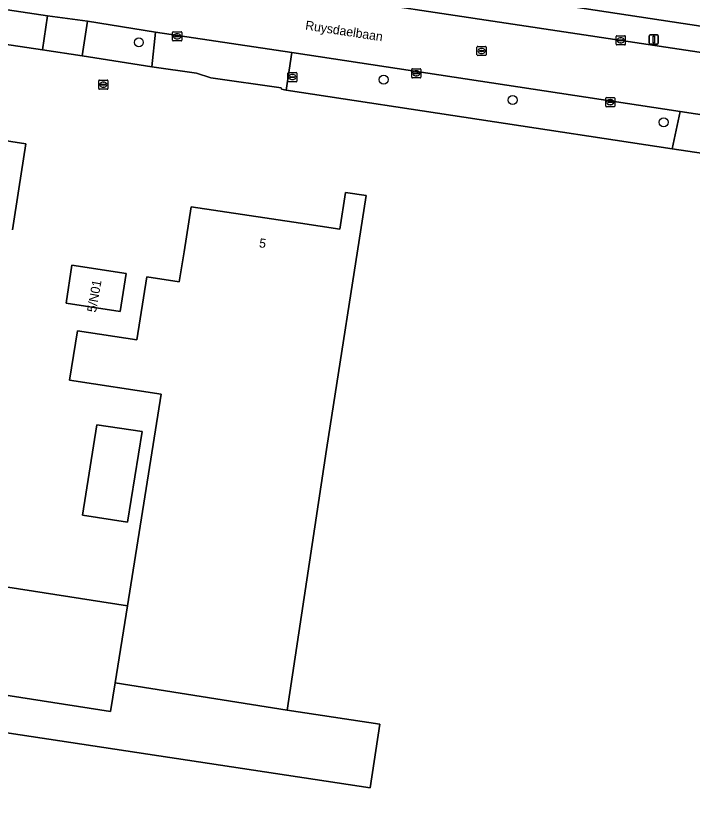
# Model space of a CAD drawing. Extents: x 163008 to 163854, y 382777 to 383982.
# Drawn here: x 163408.4 to 163482.5, y 382906.1 to 382991.6 of the extents above; entities that cross this region are included whole.
import ezdxf

# ---------------------------------------------------------------- set-up
doc = ezdxf.new("R2010")
doc.units = 0
for name, color, linetype in [('IMGEO_Berm_groen', 7, 'Continuous'), ('IMGEO_Boom', 7, 'Continuous'), ('IMGEO_Brandkraan', 7, 'Continuous'), ('IMGEO_Erf', 7, 'Continuous'), ('IMGEO_Fietspad_gesloten', 7, 'Continuous'), ('IMGEO_Kolk', 7, 'Continuous'), ('IMGEO_Lichtmast', 7, 'Continuous'), ('IMGEO_Muur', 7, 'Continuous'), ('IMGEO_Openbare_ruimte_label', 7, 'Continuous'), ('IMGEO_Pand', 7, 'Continuous'), ('IMGEO_Pand_nummerreeks', 7, 'Continuous'), ('IMGEO_Rijbaan_lokaal_gesloten', 7, 'Continuous'), ('IMGEO_Rioolput', 7, 'Continuous'), ('IMGEO_Voetpad_open', 7, 'Continuous')]:
    doc.layers.add(name, color=color, linetype=linetype)

msp = doc.modelspace()

# ---------------------------------------------------------------- linework, layer by layer
at = {"layer": 'IMGEO_Berm_groen'}
for points in [[(163489.468, 382989.524), (163415.977, 383000.7), (163414.901, 382999.838), (163414.341, 382999.01)], [(163415.02, 382997.894), (163488.831, 382986.752)]]:
    msp.add_lwpolyline(points, dxfattribs=at)
at = {"layer": 'IMGEO_Boom'}
for centre in [(163421.921, 382988.663), (163448.722, 382984.588), (163462.851, 382982.356), (163479.379, 382979.918)]:
    msp.add_circle(centre, 0.489, dxfattribs=at)
at = {"layer": 'IMGEO_Brandkraan'}
for p, q in [((163438.231, 382984.437), (163438.231, 382985.289)), ((163438.306, 382985.363), (163439.158, 382985.363)), ((163439.232, 382985.289), (163439.232, 382984.437)), ((163439.158, 382984.363), (163438.306, 382984.363)), ((163438.49, 382984.857), (163438.49, 382984.869)), ((163438.928, 382984.82), (163438.53, 382984.82)), ((163438.533, 382984.906), (163438.931, 382984.906)), ((163438.742, 382984.583), (163438.717, 382984.583)), ((163438.719, 382985.143), (163438.744, 382985.143)), ((163438.974, 382984.869), (163438.974, 382984.857))]:
    msp.add_line(p, q, dxfattribs=at)
for points in [[(163438.231, 382984.437), (163438.231, 382985.289)], [(163438.306, 382985.363), (163439.158, 382985.363)], [(163439.232, 382985.289), (163439.232, 382984.437)], [(163439.158, 382984.363), (163438.306, 382984.363)]]:
    msp.add_lwpolyline(points, dxfattribs=at)
for centre, radius, start, end in [((163438.308, 382985.287), 0.0765, 91.55205, 178.44795), ((163438.308, 382985.287), 0.0765, 91.55205, 178.44795), ((163439.156, 382985.287), 0.0765, 1.55205, 88.44795), ((163439.156, 382985.287), 0.0765, 1.55205, 88.44795), ((163438.308, 382984.439), 0.0765, 181.55205, 268.44795), ((163438.308, 382984.439), 0.0765, 181.55205, 268.44795), ((163438.53, 382984.866), 0.0403, 85.87752, 175.75265), ((163438.527, 382984.856), 0.0366, 178.93798, 274.71019), ((163438.931, 382984.863), 0.043, 264.86636, 352.45326), ((163438.935, 382984.868), 0.0386, 1.73085, 96.63898), ((163439.156, 382984.439), 0.0765, 271.55205, 358.44795), ((163439.156, 382984.439), 0.0765, 271.55205, 358.44795)]:
    msp.add_arc(centre, radius, start, end, dxfattribs=at)
for centre, major_axis, ratio, start_param, end_param in [((163438.718, 382984.863), (-0.387, 0.002), 0.722429, 4.712389, 7.853982), ((163438.743, 382984.863), (-0.39, 0.002), 0.717154, 1.570796, 4.712389)]:
    msp.add_ellipse(centre, major_axis=major_axis, ratio=ratio, start_param=start_param, end_param=end_param, dxfattribs=at)
at = {"layer": 'IMGEO_Erf'}
for points in [[(163528.59, 382970.003), (163520.158, 382971.27), (163505.535, 382973.466), (163495.471, 382975.027), (163495.486, 382974.762), (163480.305, 382977.026), (163438.054, 382983.442), (163437.535, 382983.552), (163437.517, 382983.673), (163429.788, 382984.796), (163428.242, 382985.302), (163423.358, 382986.004), (163415.703, 382987.189), (163411.357, 382987.861), (163338.968, 382998.653)], [(163388.438, 382980.834), (163409.558, 382977.575), (163408.795, 382972.634), (163408.102, 382968.143)], [(163402.396, 382929.842), (163420.669, 382927.024), (163424.375, 382950.167), (163414.343, 382951.716), (163415.208, 382957.117), (163421.702, 382956.115), (163422.808, 382963.027), (163426.346, 382962.481), (163426.869, 382965.744), (163427.66, 382970.681), (163439.625, 382968.876), (163443.926, 382968.227), (163444.531, 382972.24), (163446.825, 382971.895), (163442.466, 382944.136), (163438.164, 382915.609), (163448.299, 382914.081), (163447.247, 382907.102), (163404.085, 382913.618)]]:
    msp.add_lwpolyline(points, dxfattribs=at)
for points in [[(163413.947, 382960.143), (163414.588, 382964.296), (163420.534, 382963.378), (163419.893, 382959.225)], [(163420.687, 382936.178), (163415.745, 382936.94), (163417.329, 382946.834), (163422.271, 382946.072)]]:
    msp.add_lwpolyline(points, close=True, dxfattribs=at)
at = {"layer": 'IMGEO_Fietspad_gesloten'}
msp.add_lwpolyline([(163414.341, 382999.01), (163414.901, 382999.838), (163415.977, 383000.7), (163489.468, 382989.524), (163489.768, 382988.576), (163489.787, 382987.615)], dxfattribs=at)
at = {"layer": 'IMGEO_Kolk'}
for p, q in [((163425.617, 382988.898), (163425.617, 382989.75)), ((163425.692, 382989.824), (163426.544, 382989.824)), ((163426.105, 382989.604), (163426.13, 382989.604)), ((163426.618, 382989.75), (163426.618, 382988.898)), ((163426.544, 382988.824), (163425.692, 382988.824)), ((163425.876, 382989.318), (163425.876, 382989.33)), ((163426.314, 382989.281), (163425.916, 382989.281)), ((163425.919, 382989.367), (163426.317, 382989.367)), ((163426.128, 382989.044), (163426.103, 382989.044)), ((163426.36, 382989.33), (163426.36, 382989.318)), ((163474.179, 382988.458), (163474.179, 382989.31)), ((163474.254, 382989.384), (163475.106, 382989.384)), ((163474.438, 382988.878), (163474.438, 382988.89)), ((163474.876, 382988.841), (163474.478, 382988.841)), ((163474.481, 382988.927), (163474.879, 382988.927)), ((163474.667, 382989.164), (163474.692, 382989.164)), ((163474.922, 382988.89), (163474.922, 382988.878)), ((163475.18, 382989.31), (163475.18, 382988.458)), ((163475.106, 382988.384), (163474.254, 382988.384)), ((163474.69, 382988.604), (163474.665, 382988.604)), ((163451.794, 382984.852), (163451.794, 382985.704)), ((163451.869, 382985.778), (163452.721, 382985.778)), ((163452.053, 382985.272), (163452.053, 382985.284)), ((163452.491, 382985.235), (163452.093, 382985.235)), ((163452.096, 382985.321), (163452.494, 382985.321)), ((163452.282, 382985.558), (163452.307, 382985.558)), ((163452.537, 382985.284), (163452.537, 382985.272)), ((163452.795, 382985.704), (163452.795, 382984.852)), ((163452.721, 382984.778), (163451.869, 382984.778)), ((163452.305, 382984.998), (163452.28, 382984.998)), ((163473.032, 382981.697), (163473.032, 382982.549)), ((163473.107, 382982.623), (163473.959, 382982.623)), ((163473.291, 382982.117), (163473.291, 382982.129)), ((163473.729, 382982.08), (163473.331, 382982.08)), ((163473.334, 382982.166), (163473.732, 382982.166)), ((163473.543, 382981.843), (163473.518, 382981.843)), ((163473.52, 382982.403), (163473.545, 382982.403)), ((163473.775, 382982.129), (163473.775, 382982.117)), ((163474.033, 382982.549), (163474.033, 382981.697)), ((163473.959, 382981.623), (163473.107, 382981.623))]:
    msp.add_line(p, q, dxfattribs=at)
for points in [[(163425.617, 382988.898), (163425.617, 382989.75)], [(163425.692, 382989.824), (163426.544, 382989.824)], [(163426.618, 382989.75), (163426.618, 382988.898)], [(163426.544, 382988.824), (163425.692, 382988.824)], [(163474.179, 382988.458), (163474.179, 382989.31)], [(163474.254, 382989.384), (163475.106, 382989.384)], [(163475.18, 382989.31), (163475.18, 382988.458)], [(163475.106, 382988.384), (163474.254, 382988.384)], [(163451.794, 382984.852), (163451.794, 382985.704)], [(163451.869, 382985.778), (163452.721, 382985.778)], [(163452.795, 382985.704), (163452.795, 382984.852)], [(163452.721, 382984.778), (163451.869, 382984.778)], [(163473.032, 382981.697), (163473.032, 382982.549)], [(163473.107, 382982.623), (163473.959, 382982.623)], [(163474.033, 382982.549), (163474.033, 382981.697)], [(163473.959, 382981.623), (163473.107, 382981.623)]]:
    msp.add_lwpolyline(points, dxfattribs=at)
for centre, radius, start, end in [((163425.694, 382989.748), 0.0765, 91.55205, 178.44795), ((163425.694, 382989.748), 0.0765, 91.55205, 178.44795), ((163426.542, 382989.748), 0.0765, 1.55205, 88.44795), ((163426.542, 382989.748), 0.0765, 1.55205, 88.44795), ((163425.694, 382988.9), 0.0765, 181.55205, 268.44795), ((163425.694, 382988.9), 0.0765, 181.55205, 268.44795), ((163425.916, 382989.327), 0.0403, 85.87752, 175.75265), ((163425.913, 382989.317), 0.0366, 178.93798, 274.71019), ((163426.317, 382989.324), 0.043, 264.86636, 352.45326), ((163426.321, 382989.329), 0.0386, 1.73085, 96.63898), ((163426.542, 382988.9), 0.0765, 271.55205, 358.44795), ((163426.542, 382988.9), 0.0765, 271.55205, 358.44795), ((163474.256, 382989.308), 0.0765, 91.55205, 178.44795), ((163474.256, 382989.308), 0.0765, 91.55205, 178.44795), ((163474.478, 382988.887), 0.0403, 85.87752, 175.75265), ((163474.475, 382988.877), 0.0366, 178.93798, 274.71019), ((163474.879, 382988.884), 0.043, 264.86636, 352.45326), ((163474.883, 382988.889), 0.0386, 1.73085, 96.63898), ((163475.104, 382989.308), 0.0765, 1.55205, 88.44795), ((163475.104, 382989.308), 0.0765, 1.55205, 88.44795), ((163474.256, 382988.46), 0.0765, 181.55205, 268.44795), ((163474.256, 382988.46), 0.0765, 181.55205, 268.44795), ((163475.104, 382988.46), 0.0765, 271.55205, 358.44795), ((163475.104, 382988.46), 0.0765, 271.55205, 358.44795), ((163451.871, 382985.702), 0.0765, 91.55205, 178.44795), ((163451.871, 382985.702), 0.0765, 91.55205, 178.44795), ((163452.093, 382985.281), 0.0403, 85.87752, 175.75265), ((163452.09, 382985.271), 0.0366, 178.93798, 274.71019), ((163452.494, 382985.278), 0.043, 264.86636, 352.45326), ((163452.498, 382985.283), 0.0386, 1.73085, 96.63898), ((163452.719, 382985.702), 0.0765, 1.55205, 88.44795), ((163452.719, 382985.702), 0.0765, 1.55205, 88.44795), ((163451.871, 382984.854), 0.0765, 181.55205, 268.44795), ((163451.871, 382984.854), 0.0765, 181.55205, 268.44795), ((163452.719, 382984.854), 0.0765, 271.55205, 358.44795), ((163452.719, 382984.854), 0.0765, 271.55205, 358.44795), ((163473.109, 382982.547), 0.0765, 91.55205, 178.44795), ((163473.109, 382982.547), 0.0765, 91.55205, 178.44795), ((163473.331, 382982.126), 0.0403, 85.87752, 175.75265), ((163473.328, 382982.116), 0.0366, 178.93798, 274.71019), ((163473.732, 382982.123), 0.043, 264.86636, 352.45326), ((163473.736, 382982.128), 0.0386, 1.73085, 96.63898), ((163473.957, 382982.547), 0.0765, 1.55205, 88.44795), ((163473.957, 382982.547), 0.0765, 1.55205, 88.44795), ((163473.109, 382981.699), 0.0765, 181.55205, 268.44795), ((163473.109, 382981.699), 0.0765, 181.55205, 268.44795), ((163473.957, 382981.699), 0.0765, 271.55205, 358.44795), ((163473.957, 382981.699), 0.0765, 271.55205, 358.44795)]:
    msp.add_arc(centre, radius, start, end, dxfattribs=at)
for centre, major_axis, ratio, start_param, end_param in [((163426.104, 382989.324), (-0.387, 0.002), 0.722429, 4.712389, 7.853982), ((163426.129, 382989.324), (-0.39, 0.002), 0.717154, 1.570796, 4.712389), ((163474.666, 382988.884), (-0.387, 0.002), 0.722429, 4.712389, 7.853982), ((163474.691, 382988.884), (-0.39, 0.002), 0.717154, 1.570796, 4.712389), ((163452.281, 382985.278), (-0.387, 0.002), 0.722429, 4.712389, 7.853982), ((163452.306, 382985.278), (-0.39, 0.002), 0.717154, 1.570796, 4.712389), ((163473.519, 382982.123), (-0.387, 0.002), 0.722429, 4.712389, 7.853982), ((163473.544, 382982.123), (-0.39, 0.002), 0.717154, 1.570796, 4.712389)]:
    msp.add_ellipse(centre, major_axis=major_axis, ratio=ratio, start_param=start_param, end_param=end_param, dxfattribs=at)
at = {"layer": 'IMGEO_Lichtmast'}
for p, q in [((163477.799, 382988.581), (163477.799, 382989.381)), ((163477.799, 382989.381), (163477.799, 382988.581)), ((163477.899, 382989.481), (163478.689, 382989.481)), ((163478.689, 382989.481), (163477.899, 382989.481)), ((163478.789, 382989.381), (163478.789, 382988.581)), ((163478.789, 382988.581), (163478.789, 382989.381)), ((163478.689, 382988.481), (163477.899, 382988.481)), ((163477.899, 382988.481), (163478.689, 382988.481))]:
    msp.add_line(p, q, dxfattribs=at)
msp.add_lwpolyline([(163478.219, 382989.356), (163478.369, 382989.356), (163478.369, 382988.606), (163478.219, 382988.606), (163478.219, 382989.356)], dxfattribs=at)
for centre, start, end in [((163477.899, 382989.381), 90, 180), ((163477.899, 382989.381), 90, 180), ((163478.689, 382989.381), 0, 90), ((163478.689, 382989.381), 360, 90), ((163477.899, 382988.581), 180, 270), ((163477.899, 382988.581), 180, 270), ((163478.689, 382988.581), 270, 0), ((163478.689, 382988.581), 270, 0)]:
    msp.add_arc(centre, 0.1, start, end, dxfattribs=at)
at = {"layer": 'IMGEO_Muur'}
for points in [[(163429.788, 382984.796), (163437.517, 382983.673), (163437.535, 382983.552), (163438.054, 382983.442)], [(163438.054, 382983.442), (163480.305, 382977.026)], [(163480.305, 382977.026), (163495.486, 382974.762)]]:
    msp.add_lwpolyline(points, dxfattribs=at)
at = {"layer": 'IMGEO_Pand'}
for points in [[(163408.102, 382968.143), (163408.795, 382972.634), (163409.558, 382977.575), (163388.438, 382980.834)], [(163395.181, 382919.138), (163418.814, 382915.446), (163419.318, 382918.59), (163420.669, 382927.024), (163402.396, 382929.842)]]:
    msp.add_lwpolyline(points, dxfattribs=at)
for points in [[(163419.318, 382918.59), (163438.164, 382915.609), (163442.466, 382944.136), (163446.825, 382971.895), (163444.531, 382972.24), (163443.926, 382968.227), (163439.625, 382968.876), (163427.66, 382970.681), (163426.869, 382965.744), (163426.346, 382962.481), (163422.808, 382963.027), (163421.702, 382956.115), (163415.208, 382957.117), (163414.343, 382951.716), (163424.375, 382950.167), (163420.669, 382927.024)], [(163419.893, 382959.225), (163420.534, 382963.378), (163414.588, 382964.296), (163413.947, 382960.143)], [(163420.687, 382936.178), (163422.271, 382946.072), (163417.329, 382946.834), (163415.745, 382936.94)], [(163419.318, 382918.59), (163418.814, 382915.446), (163395.181, 382919.138), (163389.187, 382879.35), (163386.121, 382859.485), (163386.391, 382859.443), (163395.487, 382858.039), (163396.25, 382862.98), (163401.654, 382899.915), (163401.901, 382899.875), (163403.771, 382911.643), (163404.085, 382913.618), (163447.247, 382907.102), (163448.299, 382914.081), (163438.164, 382915.609)]]:
    msp.add_lwpolyline(points, close=True, dxfattribs=at)
at = {"layer": 'IMGEO_Rijbaan_lokaal_gesloten'}
for points in [[(163292.545, 383009.569), (163296.84, 383008.817), (163304.96, 383007.61), (163321.045, 383005.203), (163329.509, 383003.951), (163334.952, 383003.075), (163339.568, 383002.444), (163411.931, 382991.584), (163416.286, 382990.97), (163423.758, 382989.792), (163438.655, 382987.556), (163481.173, 382981.103), (163506.122, 382977.311), (163550.446, 382970.596), (163562.809, 382968.717), (163570.543, 382967.542), (163594.132, 382963.957), (163599.415, 382963.154), (163615.953, 382960.64), (163617.8, 382960.359)], [(163620.509, 382966.927), (163617.533, 382967.225), (163535.444, 382979.722), (163530.764, 382980.419), (163493.409, 382986.066), (163488.831, 382986.752), (163415.02, 382997.894), (163410.269, 382998.605), (163404.987, 382999.481), (163336.344, 383009.715)]]:
    msp.add_lwpolyline(points, dxfattribs=at)
at = {"layer": 'IMGEO_Rioolput'}
for p, q in [((163458.941, 382987.3), (163458.941, 382988.152)), ((163459.016, 382988.226), (163459.868, 382988.226)), ((163459.429, 382988.006), (163459.454, 382988.006)), ((163459.942, 382988.152), (163459.942, 382987.3)), ((163459.868, 382987.226), (163459.016, 382987.226)), ((163459.2, 382987.72), (163459.2, 382987.732)), ((163459.638, 382987.683), (163459.24, 382987.683)), ((163459.243, 382987.769), (163459.641, 382987.769)), ((163459.452, 382987.446), (163459.427, 382987.446)), ((163459.684, 382987.732), (163459.684, 382987.72)), ((163417.533, 382983.614), (163417.533, 382984.466)), ((163417.608, 382984.54), (163418.46, 382984.54)), ((163418.534, 382984.466), (163418.534, 382983.614)), ((163418.46, 382983.54), (163417.608, 382983.54)), ((163417.792, 382984.034), (163417.792, 382984.046)), ((163418.23, 382983.997), (163417.832, 382983.997)), ((163417.835, 382984.083), (163418.233, 382984.083)), ((163418.044, 382983.76), (163418.019, 382983.76)), ((163418.021, 382984.32), (163418.046, 382984.32)), ((163418.276, 382984.046), (163418.276, 382984.034))]:
    msp.add_line(p, q, dxfattribs=at)
for points in [[(163458.941, 382987.3), (163458.941, 382988.152)], [(163459.016, 382988.226), (163459.868, 382988.226)], [(163459.942, 382988.152), (163459.942, 382987.3)], [(163459.868, 382987.226), (163459.016, 382987.226)], [(163417.533, 382983.614), (163417.533, 382984.466)], [(163417.608, 382984.54), (163418.46, 382984.54)], [(163418.534, 382984.466), (163418.534, 382983.614)], [(163418.46, 382983.54), (163417.608, 382983.54)]]:
    msp.add_lwpolyline(points, dxfattribs=at)
for centre, radius, start, end in [((163459.018, 382988.15), 0.0765, 91.55205, 178.44795), ((163459.018, 382988.15), 0.0765, 91.55205, 178.44795), ((163459.866, 382988.15), 0.0765, 1.55205, 88.44795), ((163459.866, 382988.15), 0.0765, 1.55205, 88.44795), ((163459.018, 382987.302), 0.0765, 181.55205, 268.44795), ((163459.018, 382987.302), 0.0765, 181.55205, 268.44795), ((163459.24, 382987.729), 0.0403, 85.87752, 175.75265), ((163459.237, 382987.719), 0.0366, 178.93798, 274.71019), ((163459.641, 382987.726), 0.043, 264.86636, 352.45326), ((163459.645, 382987.731), 0.0386, 1.73085, 96.63898), ((163459.866, 382987.302), 0.0765, 271.55205, 358.44795), ((163459.866, 382987.302), 0.0765, 271.55205, 358.44795), ((163417.61, 382984.464), 0.0765, 91.55205, 178.44795), ((163417.61, 382984.464), 0.0765, 91.55205, 178.44795), ((163418.458, 382984.464), 0.0765, 1.55205, 88.44795), ((163418.458, 382984.464), 0.0765, 1.55205, 88.44795), ((163417.61, 382983.616), 0.0765, 181.55205, 268.44795), ((163417.61, 382983.616), 0.0765, 181.55205, 268.44795), ((163417.832, 382984.043), 0.0403, 85.87752, 175.75265), ((163417.829, 382984.033), 0.0366, 178.93798, 274.71019), ((163418.233, 382984.04), 0.043, 264.86636, 352.45326), ((163418.237, 382984.045), 0.0386, 1.73085, 96.63898), ((163418.458, 382983.616), 0.0765, 271.55205, 358.44795), ((163418.458, 382983.616), 0.0765, 271.55205, 358.44795)]:
    msp.add_arc(centre, radius, start, end, dxfattribs=at)
for centre, major_axis, ratio, start_param, end_param in [((163459.428, 382987.726), (-0.387, 0.002), 0.722429, 4.712389, 7.853982), ((163459.453, 382987.726), (-0.39, 0.002), 0.717154, 1.570796, 4.712389), ((163418.02, 382984.04), (-0.387, 0.002), 0.722429, 4.712389, 7.853982), ((163418.045, 382984.04), (-0.39, 0.002), 0.717154, 1.570796, 4.712389)]:
    msp.add_ellipse(centre, major_axis=major_axis, ratio=ratio, start_param=start_param, end_param=end_param, dxfattribs=at)
at = {"layer": 'IMGEO_Voetpad_open'}
for points in [[(163411.357, 382987.861), (163411.931, 382991.584), (163339.568, 383002.444), (163338.968, 382998.653)], [(163415.703, 382987.189), (163416.286, 382990.97), (163411.931, 382991.584), (163411.357, 382987.861)], [(163415.703, 382987.189), (163423.358, 382986.004), (163423.758, 382989.792), (163416.286, 382990.97)], [(163438.054, 382983.442), (163438.655, 382987.556), (163423.758, 382989.792), (163423.358, 382986.004), (163428.242, 382985.302), (163429.788, 382984.796), (163437.517, 382983.673), (163437.535, 382983.552)], [(163480.305, 382977.026), (163481.173, 382981.103), (163438.655, 382987.556), (163438.054, 382983.442)], [(163495.486, 382974.762), (163495.471, 382975.027), (163505.535, 382973.466), (163506.122, 382977.311), (163481.173, 382981.103), (163480.305, 382977.026)]]:
    msp.add_lwpolyline(points, close=True, dxfattribs=at)

# ---------------------------------------------------------------- texts
at = {"layer": 'IMGEO_Openbare_ruimte_label'}
msp.add_text('Ruysdaelbaan', height=1, rotation=351.31915, dxfattribs=at).set_placement((163440.094, 382990.068))
at = {"layer": 'IMGEO_Pand_nummerreeks'}
for s, rotation, p in [('5', 351.42124, (163435.035, 382966.251)), ('5/N01', 79.82449, (163417.215, 382959.067))]:
    msp.add_text(s, height=1, rotation=rotation, dxfattribs=at).set_placement(p)

doc.saveas('drawing.dxf')
